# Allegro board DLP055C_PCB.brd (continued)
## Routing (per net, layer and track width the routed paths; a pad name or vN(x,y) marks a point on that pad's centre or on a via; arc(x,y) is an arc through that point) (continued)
PWM_OUT_STD_0: length 40.4
  TOP w0.191: J86.1 136.12,61.05 130.35,61.05 129.53,61.86 U43.7 ; U15.W2 v1(155.45,74.9)
  BOTTOM w0.191: R640.1 J86.1 139.32,64.07 145.97,64.07 149.91,68 153.13,68 153.31,68.18 153.31,73.08 154.25,74.02 154.57,74.02 v1(155.45,74.9)
PWM_OUT_STD_1: length 69
  TOP w0.191: v1(128.37,63) 128.88,63.52 U43.8 ; U15.V2 153.92,75.4 153.49,74.96 153.49,73.34 153.39,73.24 153.39,72.04 154.12,71.31 154.12,68.51 153.79,68.18 150.25,68.18 149.7,67.64 149.7,67.62 147.32,65.23 147.32,62.14 148.23,61.22 152.04,61.22 v1(155.95,57.31)
  LY3 w0.122: J86.3 137.34,54.75 140.66,54.75 142.44,56.52 145.49,56.52 145.79,56.22 155.47,56.22 155.95,56.7 v1(155.95,57.31)
  BOTTOM w0.191: v1(128.37,63) 131.42,59.95 131.42,54.7 131.92,54.19 133.73,54.19 134.19,54.65 R632.1 J86.3
PWM_RED: length 14.5
  TOP w0.191: J97.1 138.35,50.4 138.35,52.16 137.42,53.08 134.3,53.08 133.65,53.73 133.65,55.58 132.78,56.45 U43.23
PWM_STD_0: length 13
  TOP w0.191: U43.18 v1(129.53,56.83)
  LY12 w0.122: J97.13 125.85,49.9 125.85,50.47 125.84,50.48 125.84,51.69 127.4,53.25 128.67,53.25 130.15,54.72 130.15,56.27 129.59,56.83 v1(129.53,56.83)
PWM_STD_1: length 18.2
  TOP w0.191: U43.17 v1(128.88,60.35)
  LY12 w0.122: v1(128.88,60.35) 126.04,57.51 123.21,57.51 121.84,56.14 121.84,49.97 120.84,48.97 J97.17
PWRGOOD: length 187.6
  TOP w0.191: U39.4 78.74,14.49 79.07,14.16 82.47,14.16 85.57,17.26 89.63,17.26 92.46,20.09 92.46,28.1 v1(92.55,28.19) 92.49,28.24 U13.4 ; U15.AG30 v1(163.45,103.9)
  LY3 w0.076: 140.03,95.49 140.28,95.49 140.28,95.49 140.62,95.49 140.62,95.49 143.24,95.49
  LY3 w0.102: v1(163.45,103.9) 163.93,103.42 163.93,101.91 165.12,100.72 165.12,97.21 164.31,96.4 159.92,96.4 159.36,95.84 154.65,95.84 154.19,96.3 153.77,96.3 153.77,96.3 149.57,96.3 149.56,96.3 144.06,96.3 143.24,95.49 ; 135.97,95.89 139.63,95.89 140.03,95.49
  LY3 w0.122: 135.97,95.89 129.53,95.89 129.41,95.77 98.6,95.77 97.48,96.88 v1(93.11,96.88)
  LY12 w0.122: v1(92.55,28.19) 92.55,28.3 93.37,29.12 93.37,39.07 99.79,45.5 99.79,57.62 94.26,63.15 94.26,84.54 94.57,84.85 94.57,87.11 95.4,87.94 95.4,92.87 97.1,94.57 97.1,95.08 95.3,96.88 v1(93.11,96.88)
  BOTTOM w0.191: R121.2 91.54,28.24 92.49,28.24 v1(92.55,28.19)
PWRGOOD_DRV: length 1.8
  TOP w0.191: R37.2 99.16,38.4 U14.4
PWRGOOD_LED: length 1.6
  TOP w0.191: R37.1 D5.1
REFCLKA_I: length 10.6
  TOP w0.191: R30.2 169.23,92.28 169.15,92.28 168.65,91.78 v1(168.65,91.73) 168.6,91.73 168.05,92.28 R29.2 167.55,91.87 165.42,91.87 164.95,91.4 U15.AJ18
  BOTTOM w0.191: R706.2 170.5,93.98 169.29,92.77 169.29,92.13 R655.2 169,91.73 v1(168.65,91.73)
REFCLKA_O: length 5.8
  TOP w0.191: 168.02,91.18 168.02,90.38 v1(168.07,90.33) ; 168.02,91.18 R29.1 167.03,91.24 166.86,91.4 U15.AK18 ; 168.02,91.18 169.29,91.18 R31.2
  BOTTOM w0.191: v1(168.07,90.33) 168.54,90.8 R656.2
REFCLKB_I: length 9
  TOP w0.191: U15.B16 v1(137.45,89.9)
  BOTTOM w0.191: R604.2 135.65,92.71 136.93,91.42 136.93,90.41 v1(137.45,89.9) R116.2 136.95,88.82 136.95,88.82 136.95,88.59 136.74,88.38 135.79,88.38 135.35,87.95 R118.2
REFCLKB_O: length 5.6
  TOP w0.102: U15.A16 v1(136.45,88.9)
  BOTTOM w0.102: 135.88,89.4 R116.1
  BOTTOM w0.191: v1(136.45,88.9) R116.1 135.95,90.02 135.95,90.03 135.95,91.08 135.59,91.44 R589.2 ; R117.2 135.01,89.4 135.88,89.4
RS232_VN: length 3.2
  TOP w0.191: U46.6 20.55,32.73 C694.1
RTCK: length 4.5
  BOTTOM w0.191: J501.11 77.79,19.16 R507.2 77.79,17.67 R506.1
RX0N: length 71.1
  TOP w0.127: C72.2 131.87,88.89 124.28,88.89 112.97,100.21 112.97,108.61 105.56,116.02 105.56,143.1 105.66,143.2 J3.49
RX0P: length 71.6
  TOP w0.127: J3.50 105.16,143.2 105.26,143.1 105.26,115.89 112.66,108.48 112.66,100.08 124.16,88.59 131.87,88.59 C73.2
RX1N: length 72.1
  TOP w0.127: C67.2 131.87,90.8 124.35,90.8 114.82,100.33 114.82,114.71 114.01,115.52 107.97,115.52 107.06,116.43 107.06,143.1 107.16,143.2 J3.46
RX1P: length 72.6
  TOP w0.127: J3.47 106.66,143.2 106.75,143.1 106.75,116.31 107.85,115.21 113.88,115.21 114.52,114.58 114.52,100.2 124.23,90.49 131.87,90.49 C68.2
RX2N: length 70.2
  TOP w0.127: C65.2 131.87,92.7 124.65,92.7 116.19,101.16 116.19,117.07 115.76,117.5 114.52,117.5 113.98,116.97 111.11,116.97 110.5,117.58 109.04,117.58 108.56,118.06 108.56,143.1 108.66,143.2 J3.43
RX2P: length 70.7
  TOP w0.127: J3.44 108.16,143.2 108.26,143.1 108.26,117.93 108.92,117.27 110.38,117.27 110.99,116.66 114.11,116.66 114.64,117.2 115.63,117.2 115.89,116.94 115.89,101.03 124.52,92.4 131.87,92.4 C66.2
RX3N: length 72.6
  TOP w0.127: J3.40 110.16,143.2 110.06,143.1 110.06,118.86 110.2,118.72 111.54,118.72 111.67,118.85 111.67,119.94 111.98,120.24 113.55,120.24 113.86,119.94 113.86,118.87 113.98,118.75 115.1,118.75 115.23,118.87 115.23,119.94 115.53,120.24 117.18,120.24 117.67,119.76 117.67,101.69 124.74,94.61 131.87,94.61 C63.2
RX3P: length 73.1
  TOP w0.127: J3.41 109.66,143.2 109.75,143.1 109.75,118.73 110.07,118.41 111.67,118.41 111.98,118.72 111.98,119.81 112.1,119.94 113.42,119.94 113.55,119.81 113.55,118.75 113.86,118.44 115.23,118.44 115.53,118.75 115.53,119.81 115.66,119.94 117.06,119.94 117.36,119.63 117.36,101.56 124.62,94.3 131.87,94.3 C64.2
RX4N: length 70.6
  TOP w0.127: J3.37 111.66,143.2 111.56,143.1 111.56,121.44 111.69,121.31 112.74,121.31 112.86,121.44 112.86,122.76 113.17,123.06 115.02,123.06 115.33,122.76 115.33,121.56 115.46,121.44 116.83,121.44 116.95,121.56 116.95,122.76 117.26,123.06 118.43,123.06 119.04,122.45 119.04,102.32 124.84,96.51 131.87,96.51 C61.2
RX4P: length 71.1
  TOP w0.127: J3.38 111.16,143.2 111.26,143.1 111.26,121.31 111.56,121.01 112.86,121.01 113.17,121.31 113.17,122.63 113.3,122.76 114.9,122.76 115.02,122.63 115.02,121.44 115.33,121.13 116.95,121.13 117.26,121.44 117.26,122.63 117.39,122.76 118.3,122.76 118.73,122.33 118.73,102.19 124.71,96.21 131.87,96.21 C62.2
RX5N: length 71.4
  TOP w0.127: J3.34 113.16,143.2 113.06,143.1 113.06,124.26 113.19,124.13 114.67,124.13 114.8,124.26 114.8,126.29 115.1,126.59 117.03,126.59 117.34,126.29 117.34,124.23 117.46,124.1 118.38,124.1 118.5,124.23 118.5,126.34 118.81,126.64 120.18,126.64 120.48,126.34 120.48,102.94 125,98.42 131.87,98.42 C53.2
RX5P: length 71.9
  TOP w0.127: C54.2 131.87,98.11 124.88,98.11 120.18,102.81 120.18,126.21 120.05,126.34 118.94,126.34 118.81,126.21 118.81,124.1 118.5,123.8 117.34,123.8 117.03,124.1 117.03,126.16 116.9,126.29 115.23,126.29 115.1,126.16 115.1,124.13 114.79,123.83 113.06,123.83 112.76,124.13 112.76,143.1 112.66,143.2 J3.35
RX6N: length 68.1
  TOP w0.127: J3.28 116.16,143.2 116.06,143.1 116.06,133.01 116.92,132.16 122.43,132.16 123.15,131.43 123.15,104.2 125.12,102.23 126,102.23 126.12,102.36 126.12,105.16 126.43,105.46 127.72,105.46 128.03,105.16 128.03,102.36 128.16,102.23 128.97,102.23 129.1,102.36 129.1,105.16 129.4,105.46 130.72,105.46 131.03,105.16 131.03,102.36 131.15,102.23 131.87,102.23 C49.2
RX6P: length 68.6
  TOP w0.127: C50.2 131.87,101.92 131.03,101.92 130.72,102.23 130.72,105.03 130.59,105.16 129.53,105.16 129.4,105.03 129.4,102.23 129.09,101.92 128.03,101.92 127.72,102.23 127.72,105.03 127.6,105.16 126.56,105.16 126.43,105.03 126.43,102.23 126.12,101.92 125,101.92 122.85,104.07 122.85,131.31 122.3,131.85 116.79,131.85 115.75,132.89 115.75,143.1 115.66,143.2 J3.29
RX7N: length 72.1
  TOP w0.127: C51.2 131.87,100.32 125.03,100.32 121.77,103.58 121.77,109.46 121.76,109.47 121.76,109.85 121.77,109.86 121.77,123.92 121.78,123.93 121.78,130.78 121.47,131.09 120.18,131.09 119.88,130.78 119.88,127.86 119.75,127.74 118.43,127.74 118.3,127.86 118.3,130.71 118,131.01 116.4,131.01 116.09,130.71 116.09,127.84 115.96,127.71 114.69,127.71 114.56,127.84 114.56,143.1 114.66,143.2 J3.31
RX7P: length 72.6
  TOP w0.127: C52.2 131.87,100.02 124.9,100.02 121.46,103.46 121.46,109.33 121.46,109.34 121.46,109.98 121.46,109.99 121.46,124.05 121.48,124.06 121.48,130.66 121.35,130.78 120.31,130.78 120.18,130.66 120.18,127.74 119.87,127.43 118.3,127.43 118,127.74 118,130.58 117.87,130.71 116.52,130.71 116.4,130.58 116.4,127.71 116.09,127.41 114.56,127.41 114.26,127.71 114.26,143.1 114.16,143.2 J3.32
SAS_CLK: length 105
  TOP w0.191: J28.4 179.41,7.77 179.04,8.14 178.87,8.14 TP20.1 ; U15.V4 v1(154.45,76.9)
  LY3 w0.122: v1(154.45,76.9) 154.46,76.9 154.89,77.33 154.89,79.21 155.32,79.64 158.27,79.64 160.05,81.42 165.85,81.42 166.34,80.93 v1(174.77,80.93)
  LY12 w0.122: TP20.1 174.16,12.84 174.16,16.49 173.15,17.51 173.15,25.46 173.9,26.21 173.9,29.92 173.35,30.46 173.35,36.56 170.66,39.25 170.66,47.53 171.61,48.48 171.61,56.35 171.37,56.59 171.37,73.24 173.68,75.55 173.68,79.84 v1(174.77,80.93)
SAS_CSZ: length 115.8
  TOP w0.191: v1(151.94,60.13) 151.43,60.64 148.26,60.64 146.71,62.19 146.71,65.11 149.36,67.76 149.36,67.8 149.43,67.87 149.43,71.04 149.47,71.08 149.47,71.12 149.64,71.3 149.85,71.3 150.11,71.56 151.74,71.56 152.02,71.85 152.02,72.74 152.35,73.06 152.68,73.06 152.95,73.33 U15.U1 ; J28.10 182.41,8.1 TP271.1
  LY3 w0.122: v1(151.94,60.13) 154.43,60.13 155.32,61.02 156.87,61.02 157.86,60.03 163.19,60.03 164.77,58.45 164.77,55.91 167.94,52.74 167.94,47.89 167.06,47.01 160.88,47.01 159.56,45.69 159.56,43.37 161.72,41.21 161.72,36.1 162.43,35.39 175.15,35.39 v1(175.89,34.65)
  LY12 w0.122: TP271.1 184.45,10.18 184.45,13.29 182.37,15.38 182.37,28.69 178.56,32.5 178.05,32.5 v1(175.89,34.65)
SAS_DI: length 106.1
  TOP w0.191: U15.U4 v1(153.45,76.9) ; TP270.1 177.85,12.97 177.85,11.97 180.41,9.41 J28.6
  LY3 w0.076: 158.95,77.81 158.64,77.51 158.64,77.51 158.62,77.49 158.28,77.49 158.27,77.49 157.91,77.49
  LY3 w0.102: 157.91,77.49 157.79,77.37 157.19,77.37 156.92,77.1 156.92,76.51 156.78,76.37 156.2,76.37 156,76.17 156,75.56 155.83,75.39 154.23,75.39 153.92,75.69 153.92,76.4 153.82,76.51 153.8,76.51 153.45,76.86 v1(153.45,76.9) ; 163.77,79.93 163.29,80.41 160.25,80.41 158.95,79.1 158.95,77.81
  LY3 w0.122: 163.77,79.93 166.83,79.93 166.99,80.1 v1(175.48,80.1)
  LY12 w0.122: TP270.1 176.21,21.71 175.1,22.82 175.1,33.69 174.47,34.32 174.47,36.97 172.46,38.97 172.46,43.57 172.97,44.08 172.97,45.52 172.97,45.53 172.97,46.26 173.78,47.08 173.78,49.11 173.5,49.39 173.5,52.76 174.82,54.09 174.82,79.43 v1(175.48,80.1)
SAS_DO: length 109.1
  TOP w0.191: v1(152.45,76.9) 152.45,75.9 152.95,75.4 U15.U2 ; TP268.1 180.66,10.56 181.41,9.81 J28.8
  LY3 w0.076: 159.95,77.7 159.74,77.5 159.63,77.5 159.62,77.49 159.28,77.49 159.27,77.5 158.89,77.5 158.71,77.32 158.7,77.32 158.69,77.31 158.23,77.31 157.98,77.06
  LY3 w0.102: v1(152.45,76.9) 152.84,76.51 152.84,75.84 153.87,74.81 153.94,74.81 154.3,74.44 156.68,74.44 156.97,74.73 156.97,76.19 157.22,76.43 157.6,76.43 157.98,76.81 157.98,77.06 ; 166.99,79.39 160.26,79.39 159.95,79.08 159.95,77.7
  LY3 w0.122: v1(175.96,79.43) 167.18,79.43 167.14,79.39 166.99,79.39
  LY12 w0.122: TP268.1 180.66,14.81 181.68,15.83 181.68,24.06 180.18,25.56 180.18,29.35 179.38,30.15 179.38,31.11 178.41,32.09 177.44,32.09 174.82,34.71 174.82,37.6 173.81,38.62 173.81,45.99 174.47,46.65 174.47,52.59 175.36,53.48 175.36,78.3 175.96,78.91 v1(175.96,79.43)
SAS_INTGTR_EN: length 143.9
  TOP w0.191: J28.2 178.41,7.12 178.18,7.35 175.71,7.35 175.08,7.98 175.08,11.29 TP269.1 ; U15.V3 v1(154.45,75.9) ; J21.5 v1(136.18,23.37)
  LY3 w0.122: v1(136.18,23.37) 138.27,23.37 148.13,33.23 153.19,33.23 v1(153.63,32.79)
  LY12 w0.122: v1(153.63,32.79) 154.83,33.99 154.83,44.71 152.28,47.27 149.28,47.27 148.06,48.48 144.58,48.48 143.31,49.76 143.31,49.85 143.29,49.87 143.29,51.73 143.31,51.75 143.31,51.86 143.81,52.36 143.81,53.13 146.57,55.89 146.57,57.42 146.66,57.51 146.66,58.28 146.66,58.29 146.66,58.32 146.69,58.35 146.69,58.49 148.28,60.08 148.44,60.08 148.44,60.08 150.27,60.08 152.21,62.01 153.07,62.01 153.57,62.51 153.57,62.9 155.68,65.01 155.68,65.01 156.29,65.61 156.29,65.62 156.31,65.65 156.31,66.45 153.41,69.35 153.41,74.86 v1(154.45,75.9)
  BOTTOM w0.191: v1(136.18,23.37) 136.18,19.11 140.29,14.99 141.02,14.99 143,13.01 143,10.68 143.56,10.12 160.3,10.12 164.77,14.59 171.75,14.59 TP269.1
SECONDARY_PD: length 2.7
  BOTTOM w0.191: R210.1 J82.3
SENSE_PULSE_OUT: length 28.7
  TOP w0.191: J115.12 117.68,57.17 v1(117.19,56.68) ; U49.16 v1(111.72,66.29)
  BOTTOM w0.191: J97.12 124.8,52.94 118.26,52.94 117.19,54.01 v1(117.19,56.68) 117.19,57.34 114.7,59.83 114.7,63.66 113.94,64.42 113.58,64.42 v1(111.72,66.29)
SPARE_J39_4: length 11.4
  TOP w0.191: J115.4 107.68,59.53 107.36,59.85 105.43,59.85 104.03,61.24 104.03,63.71 TP164.1
SPARE_J39_9: length 3.7
  TOP w0.191: J115.9 113.93,60.38 TP165.1
SPARE_J39_10: length 4.2
  TOP w0.191: TP166.1 115.18,59.62 J115.10
SPARE_J39_11: length 7.3
  TOP w0.191: J115.11 116.43,59.45 116.79,59.8 119.81,59.8 TP168.1
SPARE_J202_14: length 4.6
  TOP w0.191: TP153.1 124.14,51.6 J97.14
SPARE_U32_18: length 9
  TOP w0.191: J115.5 108.93,60.81 111.68,63.56 111.8,63.56 111.82,63.58 112.17,63.58 112.22,63.63 112.72,63.63 113,63.92 113,64.96 U49.18
SPARE_U39_6: length 8.9
  TOP w0.191: U43.6 130.18,66.39 130.55,66.76 134.21,66.76 134.93,66.04 TP155.1
SPARE_U39_10: length 8.6
  TOP w0.191: TP150.1 131.67,67.22 128.85,67.22 128.23,66.6 U43.9
SPARE_U39_11: length 5.3
  TOP w0.191: U43.10 127.58,67.57 TP151.1
SPARE_U39_12: length 5.3
  TOP w0.191: U43.11 126.93,67.7 TP156.1
SPARE_U39_14: length 8.7
  TOP w0.191: U43.14 126.93,60.73 126.56,61.1 126.55,61.1 TP149.1
SPARE_U39_15: length 3.5
  TOP w0.191: TP154.1 127.58,55.62 U43.15
SPARE_U39_16: length 18.7
  TOP w0.191: v1(127.71,60.38) 128.23,59.86 U43.16
  LY12 w0.122: v1(127.71,60.38) 127.66,60.38 125.83,58.56 123.19,58.56 121.08,56.45 121.08,53.78 119.81,52.51 119.81,51.35 119.84,51.32 119.84,50.47 119.81,50.44 119.81,49.86 J97.19
SPARE_U39_19: length 11.6
  TOP w0.191: v1(130.18,57.31) U43.19
  LY12 w0.122: J97.11 127.83,49.89 127.83,50.47 127.84,50.48 127.84,51.31 127.83,51.32 127.83,51.87 130.81,54.85 130.81,56.69 v1(130.18,57.31)
SPARE_U508_7: length 7.2
  TOP w0.191: U49.7 113.02,72.57 113.53,73.08 113.53,74.48 TP170.1
  BOTTOM w0.191: R661.1 114.3,74.61 TP170.1
SPARE_U508_11: length 7.8
  TOP w0.191: TP169.1 106.16,69.73 110.26,69.73 110.42,69.9 U49.11
  BOTTOM w0.191: R646.1 TP169.1
SPARE_U508_14: length 6.3
  TOP w0.191: TP163.1 107.79,63.03 109.8,63.03 109.95,63.18 109.97,63.18 110.25,63.46 110.25,63.48 110.42,63.65 U49.14
SPI0_CIPO: length 270.9
  TOP w0.191: R844.1 41.63,57.9 41.39,57.67 R845.1 R846.1 R843.1 41.39,50.25 41.4,50.24 TP273.1 v1(41.4,35.72) ; U15.AD29 v1(160.45,102.9) ; R716.1 168.31,115.18 J506.5
  LY3 w0.122: v1(41.4,35.72) 43.34,35.72 46.55,32.5 46.55,28.48 49.96,25.08 63.42,25.08 63.82,25.47 97.24,25.47 97.93,24.79 128.21,24.79 130.81,22.18 140.81,22.18 148.5,29.87 156.42,29.87 J122.6 ; v1(160.45,102.9) 161.11,103.56 161.31,103.56 161.69,103.94 161.69,104.39 161.76,104.46 161.76,105 164.05,107.3 164.05,112.43 166.57,114.94 166.57,115.1 J506.5
  LY12 w0.122: v1(160.45,102.9) 160.45,102.88 160.94,102.39 160.94,98.49 160.42,97.98 160.42,95.16 160.3,95.03 160.3,93.05 159.5,92.26 159.5,87.64 159.84,87.31 159.84,86.72 158.64,85.53 158.64,83.95 159.61,82.99 159.61,80.07 159,79.46 159,77.53 158.82,77.35 158.11,77.35 157.93,77.17 157.93,75.68 157.37,75.12 157.37,74.73 157.12,74.47 157.12,73.44 156.23,72.55 156.23,72.01 156.84,71.4 156.84,70.51 156.85,70.5 156.85,69.1 158.07,67.89 158.07,65.4 155.22,62.55 155.22,62.17 154.1,61.06 154.1,59.79 152.99,58.68 149.48,58.68 149.02,58.68 148.92,58.59 148.9,58.59 148.06,57.74 148.06,57.71 148.05,57.7 148.05,56.6 148.06,56.59 148.06,56.56 148.9,55.71 148.93,55.71 149.08,55.56 149.08,54.4 148.54,53.86 147.95,53.86 147.28,53.18 146.11,53.18 145.21,52.28 145.21,51.75 144.69,51.24 144.69,51.19 144.66,51.16 144.66,50.44 144.69,50.41 144.69,50.39 145.19,49.89 149.07,49.89 149.51,49.45 153.1,49.45 156.99,45.56 156.99,39.89 158.24,38.64 158.24,31.68 J122.6
  BOTTOM w0.191: v1(160.45,102.9) 160.32,103.03 160.32,103.83 160.47,103.98 160.47,104.31 160.48,104.32 160.48,104.66 160.77,104.95 161.54,104.95 R36.1
SPI0_CLK: length 303.4
  TOP w0.191: J506.3 171.31,115.28 R715.1 ; R847.1 R848.1 R849.1 TP274.1
  LY3 w0.122: v1(159.32,86.94) 159.32,84.88 159.76,84.44 162.95,84.44 163.5,83.88 170.41,83.88 170.74,83.55 174.93,83.55 175.31,83.93 175.31,84.36 v1(176.15,85.2) ; TP274.1 45.23,47.79 45.23,45.93 42.85,43.54 42.85,40.75 47.67,35.92 47.67,32.66 54.49,25.84 97.25,25.84 98.04,25.05 128.32,25.05 130.92,22.45 140.7,22.45 148.39,30.13 153.21,30.13 155.18,32.11 J122.5 157.86,31.4 159.36,31.4 160.63,30.13 160.63,25.76 159.97,25.1 159.97,22.67 160.73,21.9 170.1,21.9 170.79,22.59 170.79,25.28 171.55,26.04 171.55,27.64 172.51,28.61 172.51,30.13 174.62,32.24 174.62,33.36 175.36,34.1 v1(177.72,34.1)
  LY12 w0.076: 160.03,97.83 160.03,103.35 160.15,103.47 160.15,103.59
  LY12 w0.102: 160.03,97.83 160.04,97.82 160.04,93.41 159.28,92.64 159.28,86.99 v1(159.32,86.94) ; 160.15,103.59 v1(160.98,104.42)
  LY12 w0.122: v1(176.15,85.2) 176.15,81.18 176.53,80.81 176.53,52.03 175.87,51.37 175.87,47.51 174.37,46.01 174.37,38.57 176.83,36.1 176.83,34.98 v1(177.72,34.1)
  BOTTOM w0.191: R109.1 160.95,103.83 160.95,103.83 160.95,104.38 v1(160.98,104.42) 162.09,104.42 162.49,104.82 162.49,107.04 161.83,107.7 161.83,108.82 162.47,109.46 169.54,109.46 170.81,110.73 170.81,116.34 J506.3 ; R123.1 v1(176.15,85.2)
SPI0_CLK_T: length 1.4
  TOP w0.191: U15.AD28 v1(160.45,101.9)
  BOTTOM w0.191: v1(160.45,101.9) R109.2
SPI0_COPI: length 269.8
  TOP w0.191: J506.4 169.81,114.87 R714.1 ; R34.1 160.34,106.69 v1(160.25,106.6) ; TP272.1 R840.1 47.34,59.01 47.47,58.89 48.64,58.89 48.78,58.74 R841.1 R842.1 v1(50.07,55.88)
  LY3 w0.122: J122.4 156.3,33.6 154.71,32.01 152.95,32.01 151.41,30.46 148.34,30.46 140.59,22.72 131.03,22.72 128.39,25.36 119.43,25.36 117.11,27.68 87.58,27.68 86.48,26.58 65.1,26.58 62.58,29.09 61.08,29.09 57.93,32.24 v1(50.06,32.24)
  LY12 w0.076: 159.03,99.38 159.03,103.2 159.44,103.61
  LY12 w0.102: 159.44,104.09 159.44,103.61 ; 159.03,99.38 158.95,99.3 158.95,97.53 157.26,95.85 157.26,93.55 157.63,93.18 157.63,87.88 158.13,87.38
  LY12 w0.122: J122.4 155.8,34.97 155.8,39.04 155.9,39.14 155.9,45.78 152.84,48.84 149.16,48.84 148.67,49.33 144.94,49.33 144.13,50.14 144.13,50.19 144.11,50.22 144.11,51.39 144.13,51.41 144.13,51.5 144.65,52.02 144.65,52.65 145.78,53.79 146.89,53.79 147.69,54.59 147.69,56.13 147.5,56.32 147.5,56.36 147.49,56.36 147.49,57.94 147.5,57.94 147.5,57.98 147.52,58 147.52,58.14 148.62,59.24 148.79,59.24 152.32,59.24 153.49,60.41 153.49,61.25 154.41,62.16 154.41,62.56 156.02,64.17 156.03,64.17 157.12,65.27 157.12,65.27 157.15,65.3 157.15,65.31 157.32,65.48 157.32,65.53 157.48,65.69 157.48,67.62 155.46,69.64 155.46,70.12 156.08,70.74 156.08,71.37 155.62,71.83 155.62,72.59 155.62,73.2 155.96,73.54 155.96,76.24 155.98,76.26 155.98,81.99 158.13,84.13 158.13,87.38 ; v1(50.07,55.88) 50.05,55.88 49.07,54.9 49.07,37.17 48.71,36.81 48.71,33.59 v1(50.06,32.24) ; 159.44,104.09 160.31,104.97 160.31,106.55 v1(160.25,106.6)
  BOTTOM w0.191: J506.4 168.98,116.01 168.98,110.63 168.16,109.8 162.26,109.8 160.31,107.85 160.31,106.66 v1(160.25,106.6) 160.25,105.03 160.14,104.92 160.14,104.81 160.14,104.81 160.14,104.4 159.95,104.21 R110.1
SPI0_COPI_T: length 1.4
  TOP w0.191: U15.AD27 v1(160.45,100.9)
  BOTTOM w0.191: R110.2 159.95,101.4 v1(160.45,100.9)
SPI0_CSZ_0: length 312
  TOP w0.191: R717.1 166.81,115.58 J506.6 ; R850.1 TP275.1
  LY3 w0.122: v1(184.37,86.15) 184.67,85.85 184.67,46.4 181.78,43.52 181.78,36.38 175.2,29.8 175.2,28.73 174.16,27.69 174.16,25.26 170.46,21.55 160.17,21.55 159.33,22.39 159.33,25.28 160.19,26.15 160.19,27.34 159.48,28.05 147.06,28.05 140.89,21.88 130.53,21.88 127.91,24.49 97.61,24.49 96.9,25.21 63.93,25.21 62.63,23.91 45.51,23.91 40.15,29.27 40.15,36.38 41.93,38.16 41.93,45.22 43.07,46.35 TP275.1 ; v1(179.19,86.01) 178.53,86.01 175.36,82.84 167.56,82.84 167.02,83.37 159.54,83.37 158.1,84.82 158.1,86.59 v1(157.31,87.38)
  LY12 w0.076: 158.86,103.48 158.86,99.6 158.66,99.4
  LY12 w0.102: 158.86,103.48 158.99,103.61 ; v1(157.31,87.38) 157.31,93.12 157.01,93.42 157.01,97.48 158.01,98.48 158.01,99.25 158.15,99.4 158.66,99.4
  LY12 w0.122: 158.99,103.61 158.99,105.88 158.39,106.48 v1(157.95,106.48)
  BOTTOM w0.191: v1(179.19,86.01) 179.43,86.25 R122.1 180.45,86.67 183.84,86.67 v1(184.37,86.15) ; R111.1 157.95,102.4 157.95,102.83 157.95,102.83 v1(157.95,106.48) 157.95,107.97 158.59,108.62 160.5,108.62 161.64,109.76 161.64,112.05 162.86,113.27 164.41,113.27 165.25,114.11 165.25,115.27 J506.6
SPI0_CSZ_0_T: length 1.4
  TOP w0.191: U15.AB27 v1(158.45,100.9)
  BOTTOM w0.191: v1(158.45,100.9) R111.2
SPI0_CSZ_1: length 99.2
  LY12 w0.076: 159.81,98.59 159.86,98.63 159.86,103.07 159.86,103.07 159.86,104.02 159.86,104.02
  LY12 w0.122: J122.3 156.08,36.19 156.08,38.92 156.59,39.43 156.59,45.57 153.03,49.12 149.34,49.12 148.85,49.61 145.05,49.61 144.41,50.25 144.41,50.3 144.39,50.33 144.39,51.27 144.41,51.3 144.41,51.38 144.93,51.9 144.93,52.54 145.9,53.51 147.17,53.51 147.93,54.26 148.46,54.26 148.8,54.61 148.8,55.41 147.78,56.44 147.78,56.48 147.77,56.48 147.77,57.82 147.78,57.82 147.78,57.86 147.8,57.89 147.8,57.9 148.87,58.96 148.9,58.96 149.6,58.96 149.6,58.96 152.88,58.96 153.82,59.9 153.82,61.17 154.94,62.29 154.94,62.67 157.6,65.34 157.6,65.41 157.79,65.6 157.79,67.77 156.57,68.98 156.57,70.34 156.36,70.56 156.36,71.48 155.9,71.94 155.9,72.7 156.26,73.06 156.26,74 156.97,74.71 156.97,77.22 157.15,77.4 157.68,77.4 157.93,77.66 157.93,80.89 158.79,81.74 158.79,82.6 158.42,82.98 158.42,86.81 159,87.39 159,93.07 159.69,93.76 159.69,98.46 159.81,98.59 ; 159.86,104.02 161.44,105.6 162.02,105.6 163.63,107.2 v1(165,107.2)
  BOTTOM w0.191: R672.1 v1(165,107.2)
SPI0_CSZ_2: length 343.4
  TOP w0.191: R851.1 v1(13.85,53.97) ; v1(165.18,108.47) R673.1
  LY3 w0.122: v1(165.18,108.47) 171.16,108.47 175.76,113.08 175.76,129.24 173.27,131.73 173.27,134.3 171.62,135.95 171.62,141.03 168.47,144.18 163.78,144.18 163.29,144.66 159.71,144.66 158.01,142.96 148.18,142.96 144.17,146.97 140.66,146.97 131.82,138.13 129.1,138.13 127.91,139.33 127.91,141.54 128.9,142.53 128.9,144.94 125.98,147.86 104.75,147.86 104.19,148.42 87.73,148.42 87.07,147.76 86.05,147.76 85.49,148.32 79.85,148.32 79.29,147.76 48.54,147.76 46.94,149.36 5.36,149.36 3.4,147.41 3.4,137.22 1.82,135.64 1.82,57.59 10.33,49.08 12.77,49.08 13.84,50.15 13.84,53.97 v1(13.85,53.97)
  BOTTOM w0.191: TP276.1 v1(13.85,53.97)
SPI0_CSZ_3: length 140.4
  TOP w0.191: R852.1 TP277.1 ; U15.AC29 v1(159.45,102.9)
  LY3 w0.076: 158.23,101.4 158.03,101.59 158.03,102.07 158.28,102.31 158.29,102.31 158.29,102.31 159.17,102.31 159.45,102.59
  LY3 w0.102: 158.23,101.4 158.63,101.4 158.92,101.11 158.92,99.55 158.72,99.35 158.25,99.35 157.98,99.07 157.98,98.65 157.48,98.16 142.45,98.16 142.23,98.38 139.26,98.38 138.73,98.92 137.06,98.92 136.75,98.6 135.88,98.6 ; v1(159.45,102.9) 159.45,102.59
  LY3 w0.122: 135.88,98.6 135.03,98.6 134.75,98.32 133.46,98.32 133.3,98.48 120.29,98.48 119.9,98.88 98.84,98.88 93.42,104.3 91.13,104.3 88.52,106.92 87.02,106.92 84.71,109.23 81.15,109.23 80.31,110.07 73.76,110.07 72.59,111.24 71.57,111.24 71.01,110.68 71.01,109.51 71.89,108.64 71.89,103.85 71.62,103.59 71.62,102.55 69.65,100.58 68.01,100.58 66.47,102.12 62.73,102.12 60.98,100.36 55.42,100.36 54.83,99.78 54.83,94.52 TP277.1
SPI1_CIPO: length 128.6
  TOP w0.191: U15.C16 v1(138.45,89.9) ; J3.9 125.66,143.14 125.66,143.14 125.66,142.72 125.66,142.72 125.66,142.6 125.66,142.6 125.66,142.05 v1(125.69,142.01)
  LY3 w0.122: v1(126.59,89.93) 130.56,89.93 131.09,89.4 137.95,89.4 v1(138.45,89.9)
  LY12 w0.122: v1(125.69,142.01) 125.69,132.54 125.35,132.21 125.35,131 125.69,130.66 125.69,123.63 125.35,123.29 125.35,122.02 125.69,121.68 125.69,114.86 126.56,113.99 126.56,109.28 127.53,108.31 127.53,94.96 125.69,93.13 125.69,90.09 125.86,89.93 v1(126.59,89.93) ; v1(138.45,89.9) 138.98,89.36 138.98,73.34 138.55,72.91 138.55,71.38 138.98,70.95 138.98,68.3 139.26,68.02 139.26,43.27 141.22,41.31 141.22,38.84 J22.5
  BOTTOM w0.191: J22.5 144.18,37.54 R150.1
SPI1_CLK: length 131
  TOP w0.191: U15.E16 v1(140.45,89.9) ; v1(126.66,142.06) 126.66,142.62 126.66,142.63 126.66,143.04 126.66,143.04 J3.7
  LY3 w0.122: v1(140.45,89.9) 139.95,90.4 139.95,91.09 139.51,91.53 132.84,91.53 132.25,90.94 129.13,90.94 128.5,91.57 v1(126.68,91.57)
  LY12 w0.122: J22.3 144.75,38.31 142.94,38.31 141.82,39.44 141.82,41.12 142.12,41.41 142.12,41.78 140.56,43.33 140.56,48.72 140.54,48.74 140.54,52.87 140.56,52.89 140.56,65.7 141.96,67.09 141.96,71.07 141.45,71.58 141.45,72.82 140.98,73.29 140.98,89.37 v1(140.45,89.9) ; v1(126.66,142.06) 126.66,114.53 126.84,114.34 126.84,109.98 128.01,108.81 128.01,94.76 126.68,93.43 v1(126.68,91.57)
  BOTTOM w0.191: R148.1 147.18,37.08 J22.3
SPI1_COPI: length 130.9
  TOP w0.191: v1(124.65,142.01) 124.66,142.02 124.66,142.57 124.66,142.57 124.66,142.59 124.65,142.6 124.65,143.01 124.66,143.02 124.66,143.14 124.66,143.14 J3.11 ; U15.D16 v1(139.45,89.9)
  LY3 w0.122: v1(139.45,89.9) 138.94,90.4 132.85,90.4 132.69,90.56 128.3,90.56 128.13,90.73 125.91,90.73 v1(125.09,91.55)
  LY12 w0.122: v1(124.65,142.01) 124.65,127.65 124.5,127.5 124.5,126.09 124.65,125.93 124.65,110.32 126.92,108.05 126.92,95.14 125.09,93.31 v1(125.09,91.55) ; J22.4 143.63,37.93 142.72,37.93 141.54,39.11 141.54,41.78 139.56,43.75 139.56,55.67 139.55,55.69 139.55,56.07 139.56,56.09 139.56,65.36 141.31,67.11 141.31,71.11 140.84,71.59 140.3,71.59 139.97,71.92 139.97,89.38 v1(139.45,89.9)
  BOTTOM w0.191: R149.1 145.41,37.02 145.68,36.75 J22.4
SPI1_CSZ_0: length 130
  TOP w0.191: U15.B15 v1(137.45,87.9) ; v1(124.15,142.78) 124.16,142.78 J3.12
  LY3 w0.076: 135.88,88.34 135.91,88.34 135.94,88.31 137.03,88.31
  LY3 w0.102: v1(137.45,87.9) 137.03,88.31
  LY3 w0.122: v1(124.4,89.56) 125.62,88.34 128.12,88.34 128.14,88.37 128.75,88.37 128.77,88.34 135.88,88.34
  LY12 w0.122: v1(137.45,87.9) 136.93,87.38 136.93,80.57 136.77,80.41 135.94,80.41 135.43,79.91 135.43,72.48 135.96,71.96 135.96,70.5 138.77,67.69 138.77,62.97 137.97,62.16 137.97,52.52 138.91,51.58 138.91,43.13 138.4,42.62 138.4,41.1 140.86,38.64 140.86,37.71 J22.6 ; v1(124.4,89.56) 124.4,93.56 126.39,95.55 126.39,107.65 124.17,109.87 124.17,142.76 124.15,142.78 v1(124.15,142.78)
  BOTTOM w0.191: R151.1 142.88,37 142.68,36.8 J22.6
SPI1_CSZ_1: length 12.9
  TOP w0.191: U15.B17 v1(137.45,90.9) ; R38.1 TP22.1 128.4,87.63 128.41,87.64 v1(128.45,87.64)
  LY12 w0.122: v1(137.45,90.9) 136.91,90.36 133.68,90.36 130.96,87.64 v1(128.45,87.64)
SPI1_CSZ_2: length 12.1
  TOP w0.102: U15.A17 v1(136.45,89.9)
  TOP w0.191: v1(128.49,86.36) TP23.1 R39.1
  LY12 w0.122: v1(136.45,89.9) 133.83,89.9 130.29,86.36 128.5,86.36 v1(128.49,86.36)
SPI2_BC_CSZ: length 3.1
  BOTTOM w0.191: R680.1 R209.1
SPI2_CIPO: length 175.6
  TOP w0.185: J500.36 64.37,9.56 R544.1
  TOP w0.191: v1(143.19,108.27) R19.1 ; R544.1 64.82,11.81 64.82,15.99 v1(64.54,16.26)
  LY3 w0.122: v1(64.54,16.26) 62.94,17.87 52.75,17.87 52.34,17.45 J45.4
  LY5 w0.122: v1(143.19,108.27) 143.18,108.28 143.18,109.43 142.21,110.4 127.96,110.4 126.46,108.9 122.02,108.9 121.23,109.69 107.95,109.69 97.28,99.02 97.28,92.84 92.59,88.15 92.59,88.1 92.31,87.81 92.29,87.81 90.32,85.84 90.32,76.21 83.05,68.94 83.05,53.7 74.98,45.63 74.98,39.56 63.75,28.33 63.75,19.06 64.54,18.27 v1(64.54,16.26)
  BOTTOM w0.191: R19.1 v1(143.19,108.27)
SPI2_CLK: length 180.9
  TOP w0.191: R534.2 62.55,13.86 v1(62.12,14.28) 56.64,14.28 56.23,13.88 56.23,11.98 R539.2 R545.1 54.93,15.42 J45.3 ; v1(141.92,108.27) R18.1
  LY5 w0.122: v1(62.12,14.28) 62.12,12.23 62.71,11.64 66.09,11.64 69.41,14.97 72.46,14.97 76.09,18.6 88.57,18.6 93.85,23.88 93.85,34.62 93.72,34.74 93.72,73.01 98.07,77.35 98.07,84.93 97.78,85.22 97.78,89.94 98.59,90.75 98.59,95.76 105.1,102.27 127,102.27 131.16,106.43 134.34,106.43 136.37,108.47 140.86,108.47 141.06,108.27 v1(141.92,108.27)
  BOTTOM w0.191: v1(141.92,108.27) R18.1
SPI2_CLK_M: length 3.4
  TOP w0.185: J500.20 56.37,10.73 R539.1
SPI2_CLK_S: length 3.4
  TOP w0.185: J500.32 62.37,10.73 R534.1
SPI2_COPI: length 205.1
  TOP w0.185: v1(53.99,9.73) 54.37,9.34 J500.16
  TOP w0.191: R543.1 50.48,18.47 50.84,18.12 J45.5 ; v1(144.46,108.27) R20.1
  LY3 w0.122: v1(128.62,102.7) 112.42,102.7 110.36,104.76 99.18,104.76 92.5,111.44 90.36,111.44 89,112.81 75.92,112.81 v1(75.03,113.7)
  LY12 w0.122: v1(128.62,102.7) 128.62,106 129.16,106.54 132.86,106.54 133.47,107.15 143.35,107.15 144.46,108.25 v1(144.46,108.27) ; v1(53.99,9.73) 53.99,13.36 J45.5 50.84,19.33 51.89,20.38 51.89,30.18 57.1,35.39 57.1,49.82 64.76,57.49 64.76,66.17 71.73,73.14 71.73,73.75 73.83,75.85 73.83,84.01 78.02,88.2 78.02,94.42 77.62,94.83 77.62,98 77.97,98.36 77.97,98.81 77.93,98.85 77.93,103.08 77.97,103.12 77.97,112.2 76.93,113.24 75.48,113.24 v1(75.03,113.7)
  BOTTOM w0.191: R20.1 v1(144.46,108.27)
SPI2_CSZ_0: length 205.1
  TOP w0.191: R540.2 53.66,13.4 53.16,13.9 51.95,13.9 J45.6 47.94,17.91 R542.1 ; R533.2 v1(63.82,13.33) ; v1(149.07,107.61) 148.96,107.5 147.3,107.5 R22.1
  LY3 w0.122: J45.6 49.32,16.49 49.32,13.09 50.01,12.4 52.27,12.4 53.59,13.72 59.33,13.72 60.7,15.1 63.42,15.1 63.82,14.7 v1(63.82,13.33)
  LY5 w0.122: v1(63.82,13.33) 63.82,14.68 64.28,15.15 68.32,15.15 72.26,19.08 88.08,19.08 93.36,24.36 93.36,47.76 93.14,47.98 93.14,76.92 94.87,78.65 94.87,84.95 95.98,86.06 95.98,90.46 97.71,92.19 97.71,96.83 108.2,107.32 129.89,107.32 131.57,109 134.01,109 134.57,109.56 141.75,109.56 142.41,108.9 142.41,107.88 142.79,107.5 148.96,107.5 v1(149.07,107.61)
  BOTTOM w0.191: R22.1 148.66,107.2 v1(149.07,107.61)
SPI2_CSZ_0_M: length 4.2
  TOP w0.185: R540.1 54.44,10.12 54.44,9.93 54.85,9.52 55.21,9.52 55.37,9.36 J500.18
SPI2_CSZ_0_S: length 3.5
  TOP w0.185: J500.34 63.37,10.46 R533.1
SPI2_CSZ_1: length 183.7
  TOP w0.191: v1(76.4,11.54) R546.2 77.27,10.79 R200.1 ; R550.2 v1(46.37,13.22)
  TOP w0.381: R871.1 v1(145.73,105.18)
  LY3 w0.122: v1(76.4,11.54) 76.4,13.9 75.6,14.7 70.88,14.7 68.77,12.59 68.35,12.59 67.92,12.15 56.95,12.15 56.85,12.05 47.54,12.05 v1(46.37,13.22)
  LY5 w0.122: v1(76.4,11.54) 76.4,13.02 78.69,15.3 89.86,15.3 96.52,21.95 96.52,55.13 95.91,55.74 95.91,64.45 97.58,66.13 97.58,70.24 101.11,73.77 101.11,85.33 106.22,90.43 110.13,90.43 112.54,92.85 115.69,92.85 121.23,98.38 129.56,98.38 135.89,104.71 145.26,104.71 v1(145.73,105.18)
  BOTTOM w0.191: R871.1 v1(145.73,105.18)
SPI2_CSZ_1_M: length 5.4
  TOP w0.191: J500.2 47.37,8.82 TP215.1 45.4,10.79 R550.1
SPI2_CSZ_1_S: length 6
  TOP w0.191: J500.50 71.37,8.82 TP214.1 R546.1
SPI2_CSZ_2: length 182.7
  TOP w0.191: R548.2 R201.1 v1(50.77,13.22) ; R679.1 v1(143.83,111.86) ; R547.2 v1(66.99,13.51)
  LY3 w0.122: v1(66.99,13.51) 66.99,14.65 66.01,15.63 60.12,15.63 58.82,14.33 51.89,14.33 v1(50.77,13.22)
  LY5 w0.122: v1(66.99,13.51) 65.19,13.51 64.18,12.51 63.47,12.51 62.86,13.12 62.86,31.3 66.59,35.04 66.59,39.63 82.42,55.46 82.42,70.47 85.98,74.02 85.98,83.55 96.67,94.24 96.67,99.91 106.93,110.17 123.49,110.17 125.75,112.43 137.74,112.43 138.98,111.18 143.15,111.18 v1(143.83,111.86)
SPI2_CSZ_2_M: length 4.8
  TOP w0.185: J500.4 48.37,9.73 TP216.1
  TOP w0.191: R548.1 TP216.1
SPI2_CSZ_2_S: length 5.8
  TOP w0.185: J500.48 70.37,9.41 68.99,10.79 TP213.1
  TOP w0.191: R547.1 68.78,10.91 TP213.1
STATUS_INT: length 7.4
  TOP w0.191: J42.50 154.87,10.51 156.48,12.12 157.73,12.12 R627.2
SUBFRAME: length 5.4
  TOP w0.191: J97.21 TP148.1
SW_ONOFF: length 107.8
  TOP w0.191: SW3.2 4.78,138.43 4.31,138.9 4.31,143.06 4.97,143.72 6.83,143.72 J85.2 ; v1(21.45,111.28) 21.45,109.52 U26.42
  LY12 w0.122: J85.2 10.43,131.67 18.94,123.15 18.94,116.93 21.43,114.44 21.45,114.44 v1(21.45,111.28) 23.22,109.51 29.79,109.51 38.4,100.9 38.4,93.86 36.83,92.29 36.83,87.66 35.99,86.83 33.96,86.83 32.94,85.81 32.94,84.79 33.83,83.91 33.83,82.58 32.76,81.52 32.76,79.99 32.94,79.81 v1(32.94,78.85)
  BOTTOM w0.191: C585.1 21.27,111.1 v1(21.45,111.28) ; R212.2 v1(32.94,78.85)
SW_ONOFF_PD: length 9.1
  TOP w0.191: SW3.1 SW3.4 v1(14.92,135.89)
  BOTTOM w0.191: v1(14.92,135.89) R629.1
SW_ONOFF_PU: length 9.1
  TOP w0.191: SW3.3 SW3.6 v1(14.92,140.97)
  BOTTOM w0.191: R628.1 v1(14.92,140.97)
SW_PROJ_ON: length 81.7
  TOP w0.191: U2.2 v1(66.31,138.11) ; SW1.2 v1(67.3,146.05)
  LY12 w0.122: v1(40.18,85.59) 41.73,85.59 44.98,88.83 44.98,92.31 53.74,101.08 53.74,130.62 57.5,134.37 60.83,134.37 63.75,137.3 65.5,137.3 v1(66.31,138.11) 66.84,138.64 66.84,139.52 67.3,139.98 v1(67.3,146.05)
  BOTTOM w0.191: C138.2 65.2,138.11 v1(66.31,138.11) ; R217.2 v1(40.18,85.59)
SW_PROJ_ON_PD: length 8.1
  TOP w0.191: R2.1 SW1.4 SW1.1
SW_PROJ_ON_PU: length 8.1
  TOP w0.191: SW1.3 SW1.6 R1.1
TCK: length 355.4
  TOP w0.191: J20.5 v1(104.75,22.73) ; U15.AK19 v1(167.18,92.4)
  LY3 w0.122: v1(159.46,26.55) 158.9,27.11 146.5,27.11 141,21.61 130.42,21.61 127.8,24.23 106.24,24.23 v1(104.75,22.73) 103.95,23.53 97.43,23.53 93.54,19.64 76.58,19.64 75.27,20.95 J501.9 74.06,22.14 74.06,24.16 73.41,24.81 63.91,24.81 59.25,20.15 43.91,20.15 35.73,11.97 23.44,11.97 19.96,15.45 v1(11.73,15.45)
  LY12 w0.076: 165.09,92.49 164.02,92.49 163.92,92.39 163.29,92.39 163.03,92.13 163.03,91.53 162.86,91.36 162.86,90.54 162.71,90.38
  LY12 w0.102: 166.99,82.92 165.53,84.38 164.14,84.38 163.9,84.61 163.9,88.14 163.71,88.33 163.3,88.33 162.71,88.92 162.71,90.38 ; 166.99,92.4 165.18,92.4 165.09,92.49
  LY12 w0.122: v1(167.18,92.4) 166.99,92.4 ; 166.99,82.92 167.3,82.61 167.3,74.59 167.93,73.97 167.93,72.86 167.36,72.29 167.36,69.76 167.36,69.76 167.36,68.67 167.36,68.67 167.36,58.84 166.65,58.13 166.65,48.05 164.45,45.85 164.45,35.28 160.42,31.25 160.42,27.52 v1(159.46,26.55)
  BOTTOM w0.191: R517.1 75.25,17.67 R507.1 75.25,19.16 J501.9 ; v1(11.73,15.45) 10.76,14.48 8.36,14.48 6.6,16.24 6.6,23 3.57,26.03 3.57,32.73 11.24,40.4 11.24,47.55 10.05,48.75 10.05,62.74 5.65,67.14 5.65,86.27 10.18,90.8 13.58,90.8 14.03,91.25 22.81,91.25 23.95,92.39 25.35,92.39 26.93,90.8 J75.7
TDI: length 360.4
  TOP w0.191: U15.AG20 v1(163.45,93.9) ; J20.2 v1(100.99,22.7)
  LY3 w0.122: v1(100.99,22.7) 100.99,22.64 ; 100.99,22.64 100.33,21.98 97.25,21.98 94.56,19.29 71.8,19.29 70.17,20.92 J501.5 70.16,20.95 68.91,22.21 63.32,22.21 60.75,19.64 44.47,19.64 36.32,11.49 22.7,11.49 19.25,14.94 v1(12.98,14.94) ; 100.99,22.64 102.16,21.47 108.3,21.47 110.26,23.43 127.47,23.43 130.09,20.81 141.33,20.81 144.73,24.22 156.94,24.22 157.07,24.09 v1(157.07,23.53)
  LY12 w0.122: v1(163.45,93.9) 162.93,93.38 162.07,93.38 161.92,93.24 161.92,92.67 161.58,92.34 161.16,92.34 160.68,91.86 160.68,90.51 161.01,90.18 161.01,80.67 161.28,80.4 163.36,80.4 163.99,79.77 163.99,75.59 163.84,75.45 163.16,75.45 162.97,75.25 162.97,73.4 162.91,73.34 162.91,71.01 162.38,70.48 162.38,67.88 163.55,66.71 165.5,66.71 165.93,66.28 165.93,60.05 163.75,57.87 163.75,53.78 163.3,53.33 163.3,50.11 158.42,45.23 158.42,39.25 159.11,38.57 159.11,28.46 157.07,26.42 v1(157.07,23.53)
  BOTTOM w0.191: v1(12.98,14.94) 11.93,13.9 8.02,13.9 5.84,16.09 5.84,22.79 3.04,25.6 3.04,32.95 10.71,40.62 10.71,47.33 9.51,48.53 9.51,62.52 5.12,66.92 5.12,86.49 9.96,91.33 13.36,91.33 13.81,91.78 22.73,91.78 23.72,92.77 30.17,92.77 32.07,90.87 J75.3 ; R519.1 J501.5
TDO1: length 271.9
  TOP w0.191: J20.4 v1(103.5,22.69) ; U15.AG19 v1(163.45,92.9)
  LY3 w0.122: v1(163.45,92.9) 163.45,92.92 162.96,93.4 160.65,93.4 160.33,93.08 157.24,93.08 156.94,93.38 146.04,93.38 145,94.42 143.34,94.42 142.88,93.97 142.17,93.97 141.6,93.4 137.2,93.4 136.72,92.92 135.02,92.92 134.94,93.01 129.48,93.01 128.62,93.87 118.47,93.87 117.57,92.97 112.06,92.97 109.94,90.85 106.04,90.85 105.68,91.22 93.67,91.22 89.07,86.62 69.69,86.62 67.94,88.38 50.31,88.38 48.46,90.23 39.37,90.23 38.79,90.8 J75.1 ; v1(158.42,25.76) 157.7,26.48 146.24,26.48 141.11,21.34 130.31,21.34 127.69,23.96 109.55,23.96 107.59,22.01 104.18,22.01 v1(103.5,22.69)
  LY12 w0.076: 162.62,91.4 162.86,91.64 162.86,92.31
  LY12 w0.102: v1(163.45,92.9) 162.86,92.31 ; 165.93,73.43 165.93,83.07 165.21,83.79 163.75,83.79 162.98,84.57 162.98,88.21 162.46,88.72 162.46,90.01 161.96,90.51 161.96,91.13 162.23,91.4 162.62,91.4
  LY12 w0.122: v1(158.42,25.76) 158.42,26.37 160.04,28 160.04,31.61 160.22,31.78 160.22,45.58 164.31,49.66 164.31,51.24 165.06,51.99 165.06,57.22 167.08,59.24 167.08,68.78 167.08,68.79 167.08,69.64 167.08,69.65 167.08,71.59 165.93,72.74 165.93,73.43
TDO2: length 172.6
  TOP w0.191: U15.AH19 v1(163.45,91.9)
  LY3 w0.122: v1(163.45,91.9) 163.44,91.9 162.96,91.42 159.78,91.42 157.27,88.91 146.14,88.91 145.72,88.48 145.72,83.83 144.55,82.66 142.57,82.66 142.3,82.39 140.2,82.39 140,82.19 140,79.67 139.75,79.42 136.07,79.42 136.02,79.46 134.33,79.46 134.13,79.26 131.31,79.26 128.95,81.62 120.75,81.62 120.02,80.89 109.75,80.89 107.08,83.55 101.85,83.55 101.42,83.12 94.13,83.12 91.54,85.71 83.31,85.71 v1(81.96,84.36)
  LY12 w0.122: J501.13 81.66,22.28 81.66,24.57 83.41,26.32 83.41,29.68 76.25,36.84 76.25,45.81 75.1,46.95 75.1,55.05 72.77,57.39 72.77,63.06 71.29,64.54 71.29,69.6 78.23,76.54 78.23,77.76 81.96,81.49 v1(81.96,84.36)
  BOTTOM w0.191: R505.1 J501.13
TEST_SBWTCK: length 20.2
  TOP w0.191: U26.71 33.45,116.45 38.18,111.73 40.19,111.73 40.81,111.11 40.81,110.17 42.29,108.7 v1(44.37,108.7)
  LY3 w0.122: J70.8 45.12,107.95 v1(44.37,108.7)
TMP_IIC2_SCL: length 2.8
  TOP w0.191: R83.2 173.88,43.18 U34.5 174.88,44.02 v1(175.25,43.65)
TMP_IIC2_SDA: length 1.3
  TOP w0.191: R82.2 170.93,43.18 U34.4
TMS1: length 284.7
  TOP w0.191: J20.3 v1(102.24,22.68) ; v1(164.45,92.9) U15.AH20
  LY3 w0.122: v1(102.24,22.68) 103.18,21.74 107.83,21.74 109.79,23.69 127.58,23.69 130.2,21.08 141.22,21.08 144.76,24.62 157.32,24.62 v1(157.78,25.08) ; v1(164.45,92.9) 163.95,93.39 163.95,94.22 163.75,94.42 160.57,94.42 160.02,93.86 158.49,93.86 158.06,94.29 157.07,94.29 156.98,94.39 145.65,94.39 144.93,95.11 143.58,95.11 142.82,94.34 140.07,94.34 139.48,93.76 137.51,93.76 136.89,94.39 117.87,94.39 116.96,93.48 95.6,93.48 94.08,91.96 90.72,91.96 89.02,93.66 74.04,93.66 72.54,95.16 58.64,95.16 53.89,90.41 49.83,90.41 46.96,93.28 32,93.28 J75.5
  LY12 w0.122: v1(157.78,25.08) 157.78,26.37 159.58,28.18 159.58,45.45 163.95,49.82 163.95,51.42 164.78,52.24 164.78,57.7 166.7,59.62 166.7,66.89 164.83,68.75 164.83,73.31 164.97,73.46 164.97,83.01 164.57,83.41 162.3,83.41 161.97,83.74 161.97,90.12 161.7,90.38 161.18,90.38 160.96,90.61 160.96,91.17 161.24,91.45 161.79,91.45 161.99,91.65 161.99,92.19 162.24,92.44 162.68,92.44 162.93,92.69 162.93,93.06 163.26,93.39 163.96,93.39 v1(164.45,92.9)
TMS2: length 171.6
  TOP w0.191: U15.AJ20 v1(165.45,92.9)
  LY3 w0.122: v1(79.45,83.96) 81.56,86.06 91.74,86.06 94.23,83.57 101.51,83.57 101.74,83.81 108.39,83.81 108.73,83.47 109.37,83.47 109.9,82.94 110.6,82.94 110.98,82.56 117.75,82.56 118.13,82.94 119.88,82.94 120.93,81.9 129.28,81.9 130.78,80.4 138.66,80.4 138.91,80.65 138.91,83.24 139.09,83.42 141.73,83.42 142.36,84.06 142.36,85.86 143.56,87.05 143.56,88.73 144.98,90.15 144.98,90.23 146.12,91.37 157.15,91.37 157.58,91.81 158.85,91.81 159.43,92.39 164.89,92.39 165.4,92.9 v1(165.45,92.9)
  LY12 w0.122: v1(79.45,83.96) 76.25,80.76 76.25,75.73 69.24,68.72 69.24,62.37 70.66,60.94 70.66,55.76 72.92,53.5 72.92,47 73.99,45.93 73.99,22.28 72.71,21.01 J501.7
  BOTTOM w0.191: R508.1 J501.7
TMS3: length 2.4
  TOP w0.191: U15.AK20 166.18,93.17 166.35,93.17 v1(166.55,92.96)
  BOTTOM w0.191: v1(166.55,92.96) R256.1
TRSTZ: length 174.1
  TOP w0.191: U38.4 72.34,15.37 72.34,16.21 72.56,16.44 v1(73.02,16.44) ; U15.AG21 v1(162.45,93.9)
  LY3 w0.122: v1(155.83,23.25) 155.27,23.81 144.7,23.81 141.44,20.54 129.97,20.54 127.42,23.1 110.97,23.1 106.09,18.22 74.82,18.22 73.05,16.44 v1(73.02,16.44)
  LY12 w0.122: v1(162.45,93.9) 161.95,94.4 161.02,94.4 160.84,94.22 160.84,92.71 160.45,92.32 160.45,90.36 160.78,90.02 160.78,86.9 159.33,85.45 159.33,84.69 160.38,83.64 160.38,79.85 160.79,79.44 161.68,79.44 161.95,79.18 161.95,78.65 162.18,78.42 162.61,78.42 162.95,78.07 162.95,75.7 162.69,75.43 162.69,73.4 162.63,73.34 162.63,71.13 162.1,70.59 162.1,67.76 163.63,66.23 163.63,65.87 163.84,65.65 164.5,65.65 164.74,65.41 164.74,59.67 162.79,57.72 162.79,54.38 161.99,53.57 161.99,52.12 162.19,51.92 162.19,50.48 158.14,46.42 158.14,44.36 158.14,39.14 158.52,38.76 158.52,28.89 155.83,26.2 v1(155.83,23.25)
  BOTTOM w0.191: R520.2 72.71,16.13 v1(73.02,16.44)
TRSTZ_IN: length 213.6
  TOP w0.191: v1(70.49,11.27) U38.1 70.49,13.64 69.16,14.97 69.16,16.06 67.63,17.59 J501.3 ; J20.1 99.75,20.07 v1(99.88,19.94)
  LY3 w0.122: 67.63,20.87 67.63,20.85 65.68,18.91 44.9,18.91 37.05,11.06 21.94,11.06 18.64,14.36 9.52,14.36 v1(8.63,15.25) ; 67.63,20.87 J501.3 ; 67.63,20.87 69.57,18.93 95.8,18.93 96.81,19.94 v1(99.88,19.94)
  BOTTOM w0.191: R523.1 70.17,11.59 v1(70.49,11.27) ; R522.1 J501.3 ; J75.9 14.21,90.8 13.76,90.36 10.36,90.36 6.09,86.09 6.09,67.32 10.49,62.92 10.49,48.93 11.68,47.74 11.68,40.22 4.01,32.55 4.01,26.63 7.41,23.22 7.41,16.47 v1(8.63,15.25)
TSTPT_0: length 19
  TOP w0.191: U15.E29 v1(140.45,102.9)
  LY3 w0.122: v1(140.45,102.9) 139.66,103.68 139.02,103.68 136.39,106.31 136.39,115.2 J6.2
  BOTTOM w0.191: J6.2 134.07,116.14 133.82,115.89 R103.2
TSTPT_1: length 19.8
  TOP w0.191: U15.E30 v1(140.45,103.9)
  LY3 w0.122: J6.3 136.74,116.35 136.74,106.34 139.13,103.95 140.4,103.95 v1(140.45,103.9)
  BOTTOM w0.191: R101.2 133.79,117.39 134.04,117.64 J6.3
TSTPT_2: length 26.8
  TOP w0.191: U15.F26 v1(141.45,99.9)
  LY3 w0.122: J6.4 134.06,117.75 134.06,108.27 138.92,103.4 139.62,103.4 139.94,103.09 139.94,101.59 140.19,101.34 140.65,101.34 140.96,101.03 140.96,100.39 v1(141.45,99.9)
  BOTTOM w0.191: R100.2 133.92,118.89 134.17,119.14 J6.4
TSTPT_3: length 26.2
  TOP w0.191: U15.F27 v1(141.45,100.9)
  LY3 w0.076: 140.53,104.4 140.86,104.07 140.86,104.04 140.86,104.04 140.86,103.8 140.86,103.66 140.86,103.65 140.86,103.15 140.86,103.14 140.86,102.66 140.86,102.65 140.86,102.24 140.87,102.23 140.87,101.48
  LY3 w0.102: v1(141.45,100.9) 140.87,101.48 ; 140.53,104.4 139.42,104.4
  LY3 w0.122: 139.42,104.4 138.87,104.95 138.87,105.69 137.2,107.37 137.2,118.9 J6.5
  BOTTOM w0.191: J6.5 134.01,120.64 133.77,120.39 R99.2
TSTPT_4: length 26
  TOP w0.191: U15.F28 v1(141.45,101.9)
  LY3 w0.076: v1(141.45,101.9) 141.04,102.31 141.04,102.73 141.03,102.73 141.03,103.07 141.04,103.07 141.04,103.73 141.03,103.73 141.03,104.07 141.04,104.07 141.04,104.34
  LY3 w0.102: 141.04,104.34 140.92,104.46
  LY3 w0.122: J6.6 137.58,120.01 137.58,107.8 140.92,104.46
  BOTTOM w0.191: R97.2 133.79,121.89 134.04,122.14 J6.6
TSTPT_5: length 26.9
  TOP w0.191: U15.F29 v1(141.45,102.9)
  LY3 w0.122: v1(141.45,102.9) 141.91,103.37 141.91,104.18 137.93,108.16 137.93,121.16 J6.7
  BOTTOM w0.191: J6.7 134.04,123.64 133.79,123.39 R96.2
TSTPT_6: length 31.6
  TOP w0.191: U15.G26 v1(142.45,99.9)
  LY3 w0.122: J6.8 138.34,122.25 138.34,108.13 142.18,104.29 142.18,102.7 141.96,102.47 141.96,100.39 v1(142.45,99.9)
  BOTTOM w0.191: R95.2 133.74,124.89 133.99,125.14 J6.8
TSTPT_7: length 30.9
  TOP w0.191: U15.G28 v1(142.45,101.9)
  LY3 w0.122: J6.9 138.7,123.4 138.7,108.21 142.45,104.45 v1(142.45,101.9)
  BOTTOM w0.191: J6.9 134.07,126.64 133.82,126.39 R90.2
TXS_OE: length 2.4
  TOP w0.191: U34.6 174.84,44.52 v1(175.09,44.77)
  BOTTOM w0.191: R141.2 174.78,44.45 v1(175.09,44.77)
UART0_C1M: length 3.5
  TOP w0.191: v1(17.14,30.36) 17.55,30.77 U46.3
  BOTTOM w0.191: C691.1 18.73,30.36 v1(17.14,30.36)
UART0_C1P: length 3.3
  TOP w0.191: v1(20.37,29.22) 20.11,29.47 U46.1
  BOTTOM w0.191: v1(20.37,29.22) 18.84,29.22 C691.2
UART0_C2M: length 2.8
  TOP w0.191: U46.5 21.39,32.08 C693.1
UART0_C2P: length 2.8
  TOP w0.191: U46.4 21.39,31.42 C693.2
UART0_CTSZ: length 294.6
  TOP w0.191: J112.4 8.81,9.13 14.75,9.13 J104.2 ; U15.N3 v1(148.45,75.9)
  LY3 w0.076: 148.11,75.9 147.69,76.32 147.69,76.31 147.2,76.31 147.2,76.32 146.69,76.32 146.69,76.31 146.55,76.31 146.2,76.31 146.2,76.32 145.69,76.32 145.69,76.31 145.55,76.31 145.2,76.31 145.2,76.32 144.69,76.32 144.69,76.31 144.2,76.31 144.2,76.32 143.69,76.32 143.69,76.31 143.55,76.31 143.2,76.31 143.2,76.32 142.69,76.32 142.69,76.31 142.35,76.31 142.2,76.31 142.2,76.32 141.69,76.32 141.69,76.31 141.35,76.31 141.2,76.31 141.2,76.32 140.69,76.32 140.69,76.31 140.2,76.31 140.2,76.32 139.69,76.32 139.69,76.31 139.55,76.31 139.2,76.31 139.2,76.32 138.69,76.32 138.69,76.31 138.55,76.31 138.2,76.31 138.2,76.32 137.69,76.32 137.69,76.31 137.35,76.31 137.2,76.31 137.2,76.32 136.69,76.32 136.69,76.31 136.07,76.31 136.04,76.29
  LY3 w0.102: v1(148.45,75.9) 148.11,75.9 ; 136.04,76.29 135.88,76.29
  LY3 w0.122: v1(53.67,87.69) 61.87,87.69 66.7,82.86 101.53,82.86 101.96,83.29 106.98,83.29 108.88,81.38 108.88,79.17 109.14,78.92 109.14,78.9 109.7,78.34 109.71,78.34 109.74,78.32 110.61,78.32 110.63,78.34 111.4,78.34 112.29,77.45 112.67,77.45 113.17,76.96 114.18,76.96 114.19,76.97 115.82,76.97 117.01,75.78 120.21,75.78 121.81,77.38 128.77,77.38 130.61,75.54 135.07,75.54 135.81,76.29 135.88,76.29
  LY12 w0.122: v1(148.45,75.9) 148.93,75.42 149.68,75.42 150.11,74.99 150.11,73.49 149.58,72.96 149.58,72.22 148.28,70.93 148.28,65.21 148.58,64.91 148.86,64.91 149.68,64.08 149.68,64.05 149.7,64.03 149.7,62.97 149.68,62.95 149.68,62.92 148.86,62.09 148.82,62.09 148.7,61.97 147.79,61.97 145.01,59.18 145.01,59.04 144.98,59.02 144.98,58.98 144.98,58.98 144.98,58.25 142.69,55.96 142.69,55.5 142.69,55.5 142.69,52.83 142.21,52.35 142.21,52.21 142.19,52.19 142.19,49.42 142.21,49.4 142.21,48.78 143.25,47.74 143.68,47.74 144.08,47.33 146.93,47.33 148.87,45.39 149.39,45.39 151.13,43.65 151.13,41.36 151.38,41.11 151.38,38.41 152.45,37.34 152.45,24.77 151.85,24.18 J23.2 ; J104.2 15.3,10.57 15.06,10.8 15.06,13.24 15.88,14.06 J94.1 15.88,27.17 16.48,27.77 16.48,31.71 11.65,36.53 11.65,47.43 14.65,50.43 14.65,64.35 15.64,65.34 42.92,65.34 46.5,68.92 46.5,76.59 49.96,80.04 49.96,82.48 51.99,84.51 51.99,85.71 53.67,87.38 v1(53.67,87.69)
UART0_CTSZ_CON: length 12.2
  TOP w0.191: v1(10.79,32.11) 11.22,31.68 11.76,31.68 12.01,31.42 U46.13 ; J102.7 8.77,30.05 v1(9.52,30.79)
  BOTTOM w0.191: v1(10.79,32.11) 10,32.11 9.52,31.63 v1(9.52,30.79)
UART0_CTSZ_JUMPER: length 9.7
  TOP w0.191: v1(14.8,31.23) 13.95,32.08 U46.12
  LY12 w0.122: J94.2 13.33,29.76 v1(14.8,31.23)
  BOTTOM w0.191: R649.1 13.65,31.23 v1(14.8,31.23)
UART0_DCD_CON: length 8.9
  TOP w0.191: v1(9.7,25.89) J102.1
  BOTTOM w0.191: R668.1 8.51,25.89 v1(9.7,25.89)
UART0_DSR_CON: length 15.2
  TOP w0.191: v1(9.84,27.28) J102.6
  BOTTOM w0.191: v1(9.84,27.28) 8.34,27.28 R668.2 7.94,27.51 R650.2
UART0_DTR_CON: length 8.5
  TOP w0.191: v1(9.4,34.2) J102.4
  BOTTOM w0.191: v1(9.4,34.2) 7.96,34.2 R650.1
UART0_RSTZ_CON: length 11.7
  TOP w0.191: U46.14 11.99,30.77 11.81,30.59 11.49,30.59 11.49,30.6 11.22,30.6 9.57,32.25 9.57,32.43 9.17,32.82 J102.8
UART0_RTSZ: length 300.4
  TOP w0.191: v1(14.7,32.37) 14.35,32.73 U46.11 ; U15.N2 v1(148.45,74.9)
  LY3 w0.076: 135.91,75.5 136.27,75.5 136.28,75.49 136.62,75.49 136.63,75.5 137.27,75.5 137.28,75.49 137.62,75.49 137.63,75.5 138.27,75.5 138.28,75.49 138.62,75.49 138.63,75.5 139.27,75.5 139.28,75.49 139.62,75.49 139.63,75.5 140.27,75.5 140.28,75.49 140.62,75.49 140.63,75.5 141.27,75.5 141.28,75.49 141.62,75.49 141.63,75.5 142.27,75.5 142.28,75.49 142.62,75.49 142.63,75.5 143.27,75.5 143.28,75.49 143.62,75.49 143.63,75.5 144.27,75.5 144.28,75.49 144.62,75.49 144.63,75.5 145.27,75.5 145.28,75.49 145.62,75.49 145.63,75.5 146.27,75.5 146.28,75.49 146.62,75.49 146.63,75.5 146.76,75.5
  LY3 w0.102: 146.76,75.5 147.36,74.9 v1(148.45,74.9)
  LY3 w0.122: v1(52.6,87.13) 54.28,87.13 54.3,87.16 60.47,87.16 65.04,82.59 101.64,82.59 102.07,83.03 106.87,83.03 108.62,81.27 108.62,79.06 108.87,78.81 108.87,78.66 109.44,78.09 109.58,78.09 109.59,78.08 109.6,78.08 109.63,78.05 110.72,78.05 110.74,78.08 111.18,78.08 112.57,76.69 115.54,76.69 116.72,75.51 120.32,75.51 121.93,77.11 128.66,77.11 130.57,75.2 130.88,75.2 131.59,74.49 134.9,74.49 135.91,75.5
  LY12 w0.122: J23.6 145.86,24.23 151.89,30.26 151.89,37.11 150.82,38.18 150.82,39.7 149.95,40.57 146.5,40.57 146,41.06 143.82,41.06 143.53,41.36 143.53,42.54 142.31,43.76 142.31,46.24 142.05,46.5 141.66,46.89 141.66,49.17 141.64,49.19 141.64,52.41 141.66,52.43 141.66,52.59 142.13,53.06 142.13,55.27 142.13,56.19 144.21,58.27 144.21,59.28 147.58,62.65 148.63,62.65 149.12,63.15 149.12,63.18 149.14,63.2 149.14,63.8 149.12,63.82 149.12,63.85 148.63,64.35 147.92,64.35 147.89,64.33 147.84,64.33 147.42,64.75 147.42,73.87 v1(148.45,74.9) ; J104.6 14.63,6.14 14.63,7.65 13.66,8.62 11.86,8.62 J112.5 14.63,14.94 14.63,26.73 15.49,27.59 15.49,31.58 v1(14.7,32.37) 11.1,35.98 11.1,62.65 14.73,66.28 42.39,66.28 45.64,69.53 45.64,76.87 49.2,80.43 49.2,83.73 v1(52.6,87.13)
  BOTTOM w0.191: v1(14.7,32.37) 13.55,32.37 R648.1
UART0_RXD: length 266.8
  TOP w0.191: J104.5 14.41,7.86 J112.3 ; U15.P5 v1(149.45,77.9)
  LY3 w0.122: J104.5 75.06,6.07 76.3,4.83 142.41,4.83 143.98,6.4 143.98,11.02 144.93,11.97 144.93,13.62 145.72,14.41 145.72,20.59 J23.5
  LY12 w0.122: J95.1 18.06,35.6 18.06,6.82 17.31,6.07 J104.5 ; v1(149.45,77.9) 149.92,77.43 150.82,77.43 150.96,77.29 150.96,75.52 150.47,75.02 150.47,73.45 149.86,72.84 149.86,71.13 148.69,69.96 148.69,65.46 148.96,65.19 148.97,65.19 149.96,64.2 149.96,64.16 149.98,64.14 149.98,62.86 149.96,62.84 149.96,62.8 148.97,61.81 148.94,61.81 148.6,61.48 147.7,61.48 145.29,59.07 145.29,58.93 145.26,58.9 145.26,58.87 145.26,58.86 145.26,58.13 142.97,55.85 142.97,55.62 142.97,52.71 142.49,52.22 142.49,52.09 142.46,52.07 142.46,49.53 142.49,49.51 142.49,49.38 144.25,47.61 147.05,47.61 148.51,46.15 150.15,46.15 151.41,44.89 151.41,41.47 151.66,41.22 151.66,38.53 152.78,37.4 152.78,30.92 153.84,29.85 153.84,23.66 154.33,23.17 154.33,21.09 153.64,20.41 149.18,20.41 J23.5
UART0_RXD_CON: length 18
  TOP w0.191: U46.8 v1(16.3,34.03) ; v1(9.06,32.14) 8.36,31.43 J102.3
  BOTTOM w0.191: v1(16.3,34.03) 15.74,34.58 11.5,34.58 v1(9.06,32.14)
UART0_RXD_JUMPER: length 6
  TOP w0.191: U46.9 14.17,34.03 14.4,34.25 14.4,36.72 J95.2
UART0_TXD: length 272.1
  TOP w0.191: U46.10 12.93,33.36 14.58,33.36 v1(15.24,34.02) ; v1(150.45,76.9) U15.P4
  LY3 w0.122: J104.4 14.97,7.57 14.42,7.02 14.42,4.05 15.29,3.18 142.77,3.18 147.27,7.68 147.27,10.91 147.87,11.52 147.87,15.17 147.27,15.78 147.27,20.63 J23.4
  LY12 w0.122: J23.4 148.86,25.37 152.17,28.69 152.17,37.22 151.1,38.29 151.1,40.99 150.85,41.24 150.85,43.53 149.27,45.11 148.76,45.11 146.81,47.05 143.96,47.05 143.56,47.46 142.95,47.46 141.94,48.47 141.94,49.29 141.92,49.31 141.92,52.3 141.94,52.32 141.94,52.47 142.41,52.94 142.41,55.38 142.41,55.38 142.41,56.08 144.7,58.36 144.7,59.09 144.7,59.1 144.7,59.13 144.73,59.16 144.73,59.3 147.8,62.37 148.74,62.37 149.4,63.03 149.4,63.07 149.42,63.09 149.42,63.91 149.4,63.93 149.4,63.97 148.74,64.63 148,64.63 147.9,64.73 147.9,72.48 148.92,73.49 148.92,75.11 148.65,75.37 148.08,75.37 147.98,75.47 147.98,76.06 148.3,76.39 149.93,76.39 v1(150.45,76.9) ; J104.4 17.7,9.08 17.7,31.53 15.24,33.99 v1(15.24,34.02)
  BOTTOM w0.191: v1(15.24,34.02) 14.87,33.66 R647.2 ; J112.2 7.54,4.05 8.17,3.41 13.25,3.41 14.52,4.68 14.52,5.9 J104.4
